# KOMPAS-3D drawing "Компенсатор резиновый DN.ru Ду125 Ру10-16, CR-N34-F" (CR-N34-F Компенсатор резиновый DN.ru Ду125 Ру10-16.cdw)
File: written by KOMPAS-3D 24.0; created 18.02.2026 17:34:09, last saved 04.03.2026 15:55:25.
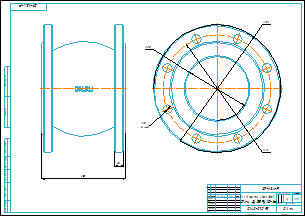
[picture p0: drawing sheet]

Document properties: Типовые: Типовые; Автор: DN.RU; Форматы листов документа: A2; Полное имя файла: CR-N34-F Компенсатор резиновый DN.ru Ду125 Ру10-16.m3d; Масса: 12; Наименование: Компенсатор резиновый DN.ru Ду125 Ру10-16; Количество листов документа: 1; Комментарий: D140-02093; Примечание: D140-02093

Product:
- Body: Твердое тело2  | qty 1
    Масса: 21.558711
- Part/product: Компенсатор резиновый DN.ru Ду125 Ру10-16  | designation CR-N34-F
    Масса: 12
    Раздел спецификации: Прочие изделия
    Комментарий: D140-02093
    Примечание: D140-02093
    additional columns: Типовые

Views: Вид 1, Спереди, Проекционный вид 2
Referenced files in E:\Работа\Зайцев\CR-N34-F Компенсатор резиновый DN.ru ДУ25-300 Ру10-16\DN125_PN10-16\: CR-N34-F Компенсатор резиновый DN.ru Ду125 Ру10-16.m3d
Referenced files in E:\Работа\Зайцев\Для компаса\: чертеж DN.ru А3.cdt
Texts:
  CR-N34-F
  чертеж DN.ru А3.cdt
  Компенсатор резиновый
  DN.ru Ду125 Ру10-16
  Твердое тело2
  Компенсатор резиновый DN.ru Ду125 Ру10-16
  CR-N34-F Компенсатор резиновый DN.ru Ду125 Ру10-16
Dimensions and other numbers on the sheet: 0; 3; 2; 4; 165; 18; 250; 210; 125; 8 отв.; 1:1; 1; 12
